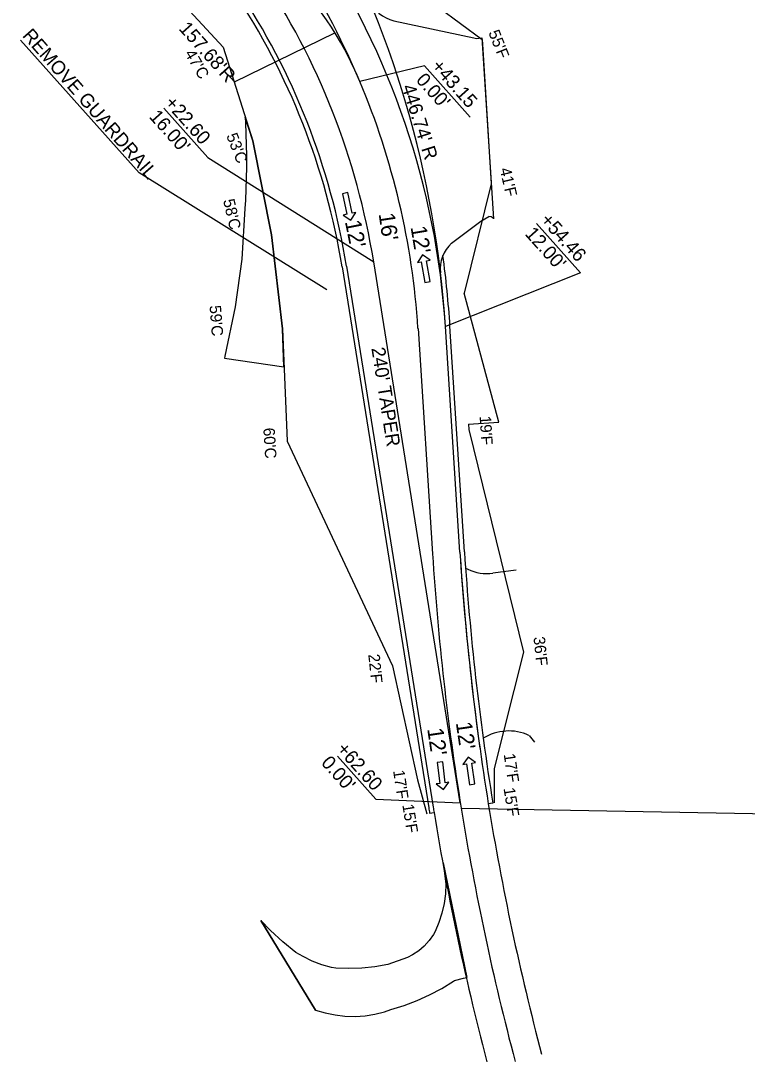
# Model space of a CAD drawing. Extents: x 1966090 to 1975830, y 788086 to 801233.
# Drawn here: x 1969330.2 to 1969647.6, y 798455.8 to 798907.3 of the extents above; entities that cross this region are included whole.
import ezdxf

# ---------------------------------------------------------------- set-up
doc = ezdxf.new("R2010")
doc.units = 0
for name, color, linetype in [('BR_PROPOSED_DRAINAGE', 7, 'Continuous'), ('RD_EX_Driveway_txCode', 7, 'Continuous'), ('RD_EX_RW_TX', 7, 'Continuous'), ('RD_EX_SU_Gas', 7, 'Continuous'), ('RD_EX_Survey_Limits', 7, 'Continuous'), ('RD_PD_PaveShd', 7, 'Continuous'), ('RD_Sketch10', 7, 'Continuous'), ('RD_Sketch4', 7, 'Continuous'), ('RD_Sketch6', 7, 'Continuous'), ('RD_Sketch8', 7, 'Continuous')]:
    doc.layers.add(name, color=color, linetype=linetype)

msp = doc.modelspace()

# ---------------------------------------------------------------- linework, layer by layer
at = {"layer": 'BR_PROPOSED_DRAINAGE'}
for p, q in [((1969382.83, 798934.48), (1969418.64, 798895.74)), ((1969418.64, 798895.74), (1969431.59, 798854.82)), ((1969532.02, 798894.68), (1969535.79, 798835.99)), ((1969431.59, 798854.82), (1969439.73, 798813.73)), ((1969535.79, 798835.99), (1969523.91, 798788.34)), ((1969439.73, 798813.73), (1969444.51, 798772.78)), ((1969539.08, 798731.91), (1969523.91, 798788.34)), ((1969444.51, 798772.78), (1969446.56, 798723.61)), ((1969525.81, 798731.01), (1969539.08, 798731.91)), ((1969525.81, 798731.01), (1969526.02, 798728.71)), ((1969526.02, 798728.71), (1969549.85, 798631.51)), ((1969446.56, 798723.61), (1969492.6, 798625.5)), ((1969549.85, 798631.51), (1969537.06, 798580.64)), ((1969492.6, 798625.5), (1969503.58, 798575.65)), ((1969537.06, 798580.64), (1969537.06, 798565.67)), ((1969503.58, 798575.65), (1969507.65, 798560.9))]:
    msp.add_line(p, q, dxfattribs=at)
msp.add_lwpolyline([(1969484.51, 798934.16), (1969531.73, 798899.07), (1969532.02, 798894.68)], dxfattribs=at)
at = {"layer": 'RD_EX_Driveway_txCode'}
for points in [[(1969473.07, 798832.24), (1969470.72, 798831.74), (1969472.61, 798822.77), (1969471.01, 798822.43), (1969474.36, 798820.25), (1969476.55, 798823.6), (1969474.96, 798823.26)], [(1969506.73, 798793.01), (1969509.09, 798793.43), (1969507.47, 798802.46), (1969509.07, 798802.75), (1969505.79, 798805.03), (1969503.5, 798801.75), (1969505.11, 798802.04)], [(1969514.55, 798583.54), (1969512.17, 798583.25), (1969513.3, 798574.15), (1969511.69, 798573.94), (1969514.85, 798571.49), (1969517.3, 798574.64), (1969515.69, 798574.44)], [(1969526.24, 798573.56), (1969528.61, 798573.9), (1969527.28, 798582.98), (1969528.89, 798583.22), (1969525.69, 798585.6), (1969523.3, 798582.4), (1969524.91, 798582.63)]]:
    msp.add_lwpolyline(points, close=True, dxfattribs=at)
at = {"layer": 'RD_EX_SU_Gas'}
for radius, start in [(345, 3.6771), (333, 22.8293)]:
    msp.add_arc((1969171.45, 798751.56), radius, start, 33.7837, dxfattribs=at)
at = {"layer": 'RD_EX_Survey_Limits'}
for p, q in [((1969522.26, 798565.7), (1969484.41, 798802.02)), ((1969503.77, 798772.92), (1969510.1, 798674.37))]:
    msp.add_line(p, q, dxfattribs=at)
for centre, radius, start, end in [((1969333.04, 798819.58), 157.68, 22.8293, 45.0596), ((1969171.45, 798751.56), 317, 9.1587, 33.7837), ((1969171.45, 798751.56), 333, 3.6771, 22.8293), ((1970664.64, 798748.57), 1156.92, 183.67706, 189.21347), ((1970664.64, 798748.57), 1156.92, 189.21347, 194.81615)]:
    msp.add_arc(centre, radius, start, end, dxfattribs=at)
at = {"layer": 'RD_PD_PaveShd'}
for p, q in [((1969470.59, 798799.79), (1969508.44, 798563.49)), ((1969524.07, 798675.27), (1969517.74, 798773.82)), ((1969536.46, 798565.57), (1969534.49, 798565.25)), ((1969508.82, 798561.09), (1969510.8, 798561.41))]:
    msp.add_line(p, q, dxfattribs=at)
for centre, radius, start, end in [((1969171.45, 798751.56), 303, 9.1587, 33.7837), ((1969069.93, 798745.04), 448.74, 3.6771, 7.6498), ((1970664.64, 798748.57), 1142.92, 183.67706, 189.21347), ((1970664.64, 798748.57), 1170.92, 189.09461, 189.21347)]:
    msp.add_arc(centre, radius, start, end, dxfattribs=at)
at = {"layer": 'RD_Sketch10'}
for p, q in [((1969431.59, 798854.82), (1969428.3, 798865.22)), ((1969439.73, 798813.73), (1969431.59, 798854.82)), ((1969431.59, 798854.82), (1969431.59, 798854.82)), ((1969431.59, 798854.82), (1969431.59, 798854.82)), ((1969439.73, 798813.73), (1969439.73, 798813.73)), ((1969439.73, 798813.73), (1969439.73, 798813.73)), ((1969419.22, 798759.91), (1969419.24, 798759.91)), ((1969419.24, 798759.91), (1969445.2, 798756.1)), ((1969514.81, 798539.48), (1969525.15, 798489.34)), ((1969525.15, 798489.34), (1969514.81, 798539.48)), ((1969459.06, 798475.14), (1969435.12, 798514.22)), ((1969435.12, 798514.22), (1969459.06, 798475.14))]:
    msp.add_line(p, q, dxfattribs=at)
for points in [[(1969428.3, 798865.22), (1969428.43, 798862.72), (1969428.61, 798857.89), (1969428.74, 798853.05), (1969428.79, 798848.22), (1969428.78, 798843.38), (1969428.71, 798838.54), (1969428.56, 798833.71), (1969428.36, 798828.88), (1969428.16, 798825.25), (1969426.88, 798803.13), (1969423.84, 798782.36), (1969419.42, 798760.74), (1969419.22, 798759.91)], [(1969445.2, 798756.1), (1969444.51, 798772.78), (1969439.73, 798813.73)], [(1969514.81, 798539.48), (1969515.91, 798530.25), (1969515.74, 798525.95), (1969515.18, 798521.68), (1969514.23, 798517.48), (1969512.9, 798513.38), (1969511.2, 798509.43), (1969510.52, 798508.07), (1969508.67, 798505.45), (1969506.51, 798503.07), (1969504.08, 798500.98), (1969501.41, 798499.2), (1969499.2, 798498.06), (1969490.56, 798495.03), (1969484.95, 798494.05), (1969479.29, 798493.47), (1969473.6, 798493.28), (1969467.91, 798493.49), (1969466, 798493.65), (1969461.72, 798494.89), (1969457.57, 798496.5), (1969453.58, 798498.48), (1969450.47, 798500.34), (1969444.79, 798504.99), (1969439.37, 798509.94), (1969435.12, 798514.22)], [(1969459.06, 798475.14), (1969463.25, 798473.87), (1969467.53, 798472.98), (1969471.88, 798472.48), (1969476.25, 798472.38), (1969480.62, 798472.66), (1969484.94, 798473.34), (1969489.18, 798474.41), (1969491.92, 798475.32), (1969497.7, 798477.09), (1969503.35, 798479.24), (1969508.85, 798481.75), (1969514.18, 798484.61), (1969519.3, 798487.81), (1969519.74, 798488.11), (1969523.66, 798489), (1969525.15, 798489.34)]]:
    msp.add_lwpolyline(points, dxfattribs=at)
at = {"layer": 'RD_Sketch4'}
for p, q in [((1969493.26, 798907.33), (1969528.17, 798899.83)), ((1969528.17, 798899.83), (1969529.32, 798899.58)), ((1969529.32, 798899.58), (1969531.69, 798899.82)), ((1969531.69, 798899.82), (1969536.76, 798820.83)), ((1969518.45, 798810.1), (1969531.19, 798819.76)), ((1969531.19, 798819.76), (1969534.78, 798821.75)), ((1969535.76, 798821.59), (1969534.78, 798821.75)), ((1969536.59, 798821.07), (1969535.76, 798821.59)), ((1969536.76, 798820.83), (1969536.59, 798821.07)), ((1969524.55, 798668.15), (1969525.56, 798667.69)), ((1969546.67, 798667.25), (1969536.51, 798665.97)), ((1969552.26, 798595.13), (1969554.68, 798592.22))]:
    msp.add_line(p, q, dxfattribs=at)
for centre, radius, start, end in [((1969496.41, 798921.99), 15, 202.5345, 257.8806), ((1969528.5, 798798.97), 15, 132.0785, 186.7079), ((1969534, 798685.81), 20, 245.0108, 277.1826), ((1969543.44, 798575.71), 21.33, 65.5808, 121.6889)]:
    msp.add_arc(centre, radius, start, end, dxfattribs=at)
at = {"layer": 'RD_Sketch6'}
for p, q in [((1969382.03, 798840.8), (1969330.2, 798898.84)), ((1969506.63, 798887.53), (1969478.37, 798880.76)), ((1969526.61, 798865.15), (1969506.63, 798887.53)), ((1969411.95, 798847.56), (1969392.76, 798869.05)), ((1969411.95, 798847.56), (1969484.41, 798802.02)), ((1969463.9, 798789.77), (1969382.03, 798840.8)), ((1969574.77, 798797.2), (1969555.51, 798818.78)), ((1969574.77, 798797.2), (1969515.74, 798773.69)), ((1969485.37, 798567.31), (1969468.61, 798586.08)), ((1969485.37, 798567.31), (1969522.26, 798565.7)), ((1969522.64, 798563.33), (1969797.07, 798558.42))]:
    msp.add_line(p, q, dxfattribs=at)
msp.add_lwpolyline([(1969420.82, 798883.7), (1969423.59, 798880.59), (1969467.45, 798902.03)], dxfattribs=at)
at = {"layer": 'RD_Sketch8'}
for p, q in [((1969472.56, 798800.11), (1969510.41, 798563.8)), ((1969522.08, 798675.14), (1969515.74, 798773.69))]:
    msp.add_line(p, q, dxfattribs=at)
for centre, radius, start, end in [((1969069.93, 798745.04), 446.74, 3.6771, 29.1352), ((1969171.45, 798751.56), 305, 9.1587, 33.7837), ((1970664.64, 798748.57), 1144.92, 183.67706, 187.98749), ((1970664.64, 798748.57), 1144.92, 183.67706, 189.21347), ((1970664.64, 798748.57), 1168.92, 189.09461, 189.21347), ((1970664.64, 798748.57), 1168.92, 189.21347, 194.81615), ((1970664.64, 798748.57), 1144.92, 189.21347, 194.81615)]:
    msp.add_arc(centre, radius, start, end, dxfattribs=at)

# ---------------------------------------------------------------- texts
at = {"layer": 'RD_EX_Driveway_txCode'}
for s, rotation, p in [("16'", 278.3209, (1969486.56, 798822.91)), ("12'", 281.515, (1969471.81, 798819.55)), ("12'", 279.4346, (1969500.49, 798817.18)), ("12'", 278.3209, (1969507.79, 798597.94)), ("12'", 278.3209, (1969520.27, 798600.63))]:
    msp.add_text(s, height=7, rotation=rotation, dxfattribs=at).set_placement(p)
at = {"layer": 'RD_EX_RW_TX'}
for s, rotation, p in [("55'F", 291.6502, (1969534.44, 798902.13)), ("47'C", 300.2531, (1969401.71, 798892.98)), ("53'C", 291.6502, (1969419.93, 798857.08)), ("41'F", 283.0472, (1969539.41, 798842.53)), ("58'C", 283.0472, (1969418.6, 798828.85)), ("59'C", 274.4442, (1969412.69, 798782.81)), ("19'F", 273.6771, (1969530.66, 798734.57)), ("60'C", 273.6771, (1969436.17, 798729.36)), ("36'F", 275.9944, (1969554.19, 798638.03)), ("22'F", 275.9944, (1969482.02, 798630.45)), ("17'F", 278.4706, (1969541.19, 798586.87)), ("17'F", 278.4706, (1969492.87, 798579.67)), ("15'F", 279.2135, (1969541.11, 798571.95)), ("15'F", 279.2135, (1969496.89, 798564.77))]:
    msp.add_text(s, height=5, rotation=rotation, dxfattribs=at).set_placement(p)
at = {"layer": 'RD_Sketch6'}
for s, height, rotation, p in [('REMOVE GUARDRAIL', 5.9996, 311.2353, (1969330.64, 798900.62)), ("157.68'R", 6, 311.7255, (1969399, 798903.65)), ('+43.15', 6, 311.7606, (1969509.28, 798887.17)), ("0.00'", 6, 311.7606, (1969502.57, 798881.18)), ("446.74' R", 6, 287.5262, (1969496.63, 798878.5)), ('+22.60', 6, 311.7606, (1969392.71, 798871.17)), ("16.00'", 6, 311.7606, (1969386, 798865.17)), ('+54.46', 6, 311.7606, (1969556.87, 798819.99)), ("12.00'", 6, 311.7606, (1969550.16, 798814)), ("240' TAPER", 6, 278.9328, (1969483.38, 798764.23)), ('+62.60', 6, 311.7606, (1969467.85, 798588.89)), ("0.00'", 6, 311.7606, (1969461.14, 798582.9))]:
    msp.add_text(s, height=height, rotation=rotation, dxfattribs=at).set_placement(p)

doc.saveas('drawing.dxf')
